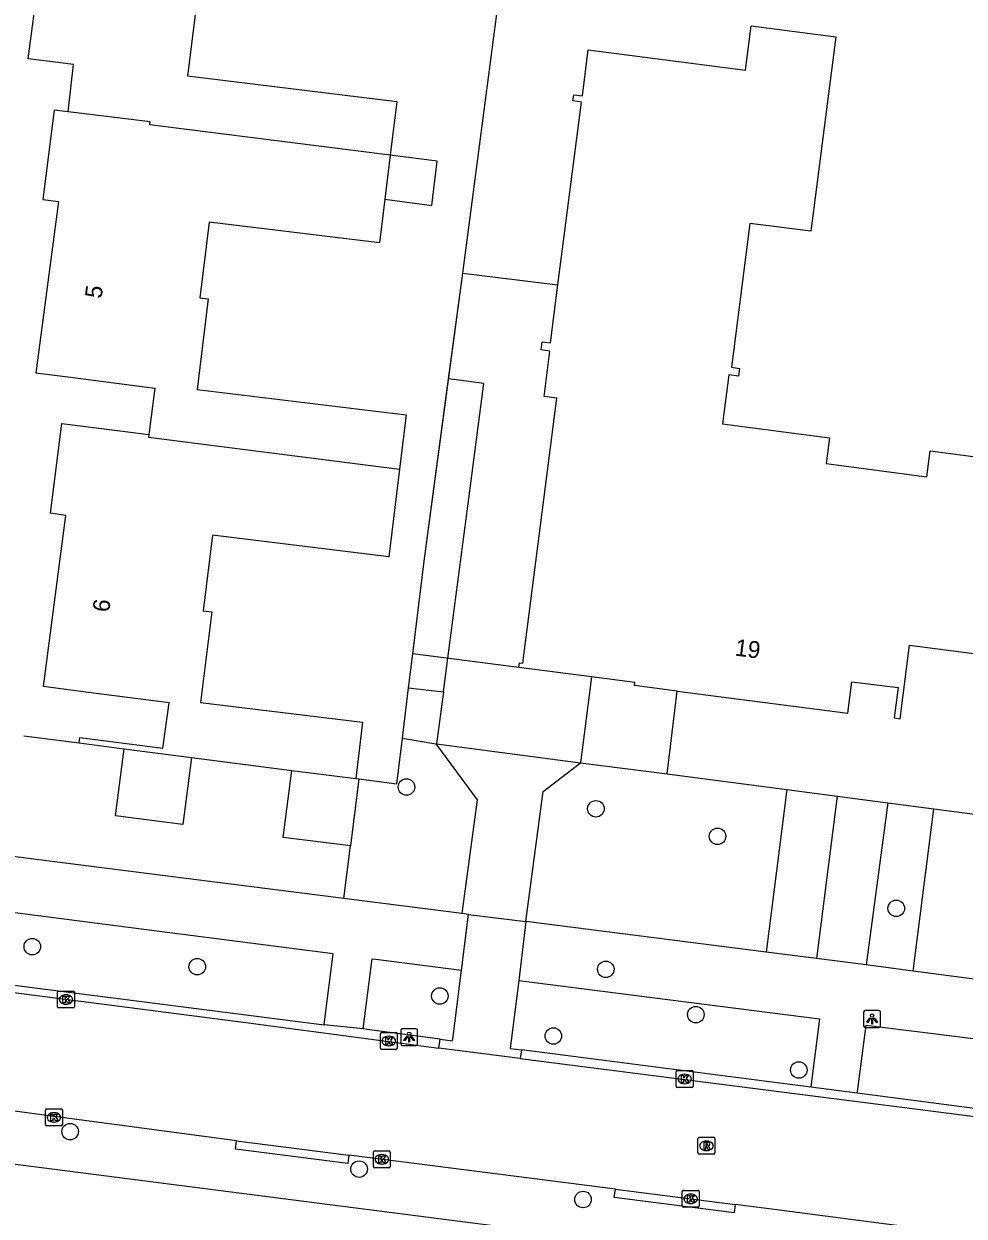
# Model space of a CAD drawing. Extents: x 162186 to 163152, y 385513 to 386513.
# Drawn here: x 162428.7 to 162484.4, y 386032.3 to 386102.8 of the extents above; entities that cross this region are included whole.
import ezdxf

# ---------------------------------------------------------------- set-up
doc = ezdxf.new("R2010")
doc.units = 0
for name, color, linetype in [('IMGEO_Boom', 7, 'Continuous'), ('IMGEO_Groenvoorziening', 7, 'Continuous'), ('IMGEO_Hek', 7, 'Continuous'), ('IMGEO_Kolk', 7, 'Continuous'), ('IMGEO_Lichtpunt', 7, 'Continuous'), ('IMGEO_Pand', 7, 'Continuous'), ('IMGEO_Pand_nummerreeks', 7, 'Continuous'), ('IMGEO_Parkeervlak_open', 7, 'Continuous'), ('IMGEO_Rijbaan_lokaal_open', 7, 'Continuous'), ('IMGEO_Rioolput', 7, 'Continuous'), ('IMGEO_Voetpad_open', 7, 'Continuous')]:
    doc.layers.add(name, color=color, linetype=linetype)

msp = doc.modelspace()

# ---------------------------------------------------------------- linework, layer by layer
at = {"layer": 'IMGEO_Boom'}
for centre in [(162451.366, 386057.668), (162462.574, 386056.38), (162469.77, 386054.75), (162480.341, 386050.488), (162429.227, 386048.224), (162438.987, 386047.037), (162463.156, 386046.884), (162453.342, 386045.303), (162468.485, 386044.202), (162460.056, 386042.937), (162474.576, 386040.923), (162431.465, 386037.28), (162448.562, 386035.061), (162461.812, 386033.263)]:
    msp.add_circle(centre, 0.489, dxfattribs=at)
at = {"layer": 'IMGEO_Groenvoorziening'}
for points in [[(162428.719, 386060.699), (162431.998, 386060.278)], [(162448.556, 386058.142), (162450.787, 386057.854), (162451.121, 386060.554)], [(162438.638, 386059.421), (162438.126, 386055.454), (162434.159, 386055.966), (162434.67, 386059.933)], [(162448.046, 386054.19), (162444.077, 386054.687), (162444.589, 386058.654)], [(162466.784, 386058.45), (162473.878, 386057.522)], [(162448.556, 386058.142), (162448.046, 386054.19)], [(162448.363, 386058.167), (162448.556, 386058.142)], [(162473.878, 386057.522), (162472.641, 386047.895)], [(162473.878, 386057.522), (162476.853, 386057.133)], [(162479.853, 386056.74), (162482.563, 386056.386)], [(162481.339, 386046.773), (162482.563, 386056.386)], [(162482.563, 386056.386), (162495.261, 386054.726), (162500, 386054.106), (162515.064, 386052.135), (162521.578, 386051.283), (162521.727, 386051.263)], [(162447.668, 386051.07), (162448.046, 386054.19)]]:
    msp.add_lwpolyline(points, dxfattribs=at)
at = {"layer": 'IMGEO_Hek'}
for points in [[(162454.696, 386088.073), (162457.574, 386110.037)], [(162452.419, 386071.03), (162454.696, 386088.073)], [(162454.696, 386088.073), (162460.323, 386087.377)], [(162458.017, 386064.739), (162451.74, 386065.549)]]:
    msp.add_lwpolyline(points, dxfattribs=at)
at = {"layer": 'IMGEO_Kolk'}
for p, q in [((162430.723, 386044.669), (162430.723, 386045.521)), ((162430.798, 386045.595), (162431.65, 386045.595)), ((162431.211, 386045.375), (162431.236, 386045.375)), ((162431.724, 386045.521), (162431.724, 386044.669)), ((162431.65, 386044.595), (162430.798, 386044.595)), ((162431.234, 386044.815), (162431.209, 386044.815)), ((162449.822, 386042.214), (162449.822, 386043.066)), ((162449.897, 386043.14), (162450.749, 386043.14)), ((162450.31, 386042.92), (162450.335, 386042.92)), ((162450.823, 386043.066), (162450.823, 386042.214)), ((162450.749, 386042.14), (162449.897, 386042.14)), ((162450.333, 386042.36), (162450.308, 386042.36)), ((162467.32, 386039.968), (162467.32, 386040.82)), ((162467.395, 386040.894), (162468.247, 386040.894)), ((162468.321, 386040.82), (162468.321, 386039.968)), ((162467.831, 386040.114), (162467.806, 386040.114)), ((162467.808, 386040.674), (162467.833, 386040.674)), ((162468.247, 386039.894), (162467.395, 386039.894)), ((162430.081, 386038.621), (162430.933, 386038.621)), ((162430.006, 386037.695), (162430.006, 386038.547)), ((162430.494, 386038.401), (162430.519, 386038.401)), ((162431.007, 386038.547), (162431.007, 386037.695)), ((162430.933, 386037.621), (162430.081, 386037.621)), ((162430.517, 386037.841), (162430.492, 386037.841)), ((162449.409, 386035.217), (162449.409, 386036.069)), ((162449.484, 386036.143), (162450.336, 386036.143)), ((162449.897, 386035.923), (162449.922, 386035.923)), ((162450.41, 386036.069), (162450.41, 386035.217)), ((162450.336, 386035.143), (162449.484, 386035.143)), ((162449.92, 386035.363), (162449.895, 386035.363)), ((162467.678, 386032.88), (162467.678, 386033.732)), ((162467.753, 386033.806), (162468.605, 386033.806)), ((162468.679, 386033.732), (162468.679, 386032.88)), ((162468.189, 386033.026), (162468.164, 386033.026)), ((162468.166, 386033.586), (162468.191, 386033.586)), ((162468.605, 386032.806), (162467.753, 386032.806))]:
    msp.add_line(p, q, dxfattribs=at)
for points in [[(162430.723, 386044.669), (162430.723, 386045.521)], [(162430.798, 386045.595), (162431.65, 386045.595)], [(162431.044, 386045.295), (162431.167, 386045.295), (162431.167, 386045.144), (162431.297, 386045.295), (162431.461, 386045.295), (162431.315, 386045.144), (162431.468, 386044.895), (162431.316, 386044.895), (162431.231, 386045.059), (162431.167, 386044.992), (162431.167, 386044.895), (162431.044, 386044.895), (162431.044, 386045.295)], [(162431.724, 386045.521), (162431.724, 386044.669)], [(162431.65, 386044.595), (162430.798, 386044.595)], [(162449.822, 386042.214), (162449.822, 386043.066)], [(162449.897, 386043.14), (162450.749, 386043.14)], [(162450.143, 386042.84), (162450.266, 386042.84), (162450.266, 386042.689), (162450.396, 386042.84), (162450.56, 386042.84), (162450.414, 386042.689), (162450.567, 386042.44), (162450.415, 386042.44), (162450.33, 386042.604), (162450.266, 386042.537), (162450.266, 386042.44), (162450.143, 386042.44), (162450.143, 386042.84)], [(162450.823, 386043.066), (162450.823, 386042.214)], [(162450.749, 386042.14), (162449.897, 386042.14)], [(162467.32, 386039.968), (162467.32, 386040.82)], [(162467.395, 386040.894), (162468.247, 386040.894)], [(162468.321, 386040.82), (162468.321, 386039.968)], [(162467.641, 386040.594), (162467.764, 386040.594), (162467.764, 386040.443), (162467.894, 386040.594), (162468.058, 386040.594), (162467.912, 386040.443), (162468.065, 386040.194), (162467.913, 386040.194), (162467.828, 386040.358), (162467.764, 386040.291), (162467.764, 386040.194), (162467.641, 386040.194), (162467.641, 386040.594)], [(162468.247, 386039.894), (162467.395, 386039.894)], [(162430.081, 386038.621), (162430.933, 386038.621)], [(162430.006, 386037.695), (162430.006, 386038.547)], [(162430.327, 386038.321), (162430.45, 386038.321), (162430.45, 386038.17), (162430.58, 386038.321), (162430.744, 386038.321), (162430.598, 386038.17), (162430.751, 386037.921), (162430.599, 386037.921), (162430.514, 386038.085), (162430.45, 386038.018), (162430.45, 386037.921), (162430.327, 386037.921), (162430.327, 386038.321)], [(162431.007, 386038.547), (162431.007, 386037.695)], [(162430.933, 386037.621), (162430.081, 386037.621)], [(162449.409, 386035.217), (162449.409, 386036.069)], [(162449.484, 386036.143), (162450.336, 386036.143)], [(162449.73, 386035.843), (162449.853, 386035.843), (162449.853, 386035.692), (162449.983, 386035.843), (162450.147, 386035.843), (162450.001, 386035.692), (162450.154, 386035.443), (162450.002, 386035.443), (162449.917, 386035.607), (162449.853, 386035.54), (162449.853, 386035.443), (162449.73, 386035.443), (162449.73, 386035.843)], [(162450.41, 386036.069), (162450.41, 386035.217)], [(162450.336, 386035.143), (162449.484, 386035.143)], [(162467.678, 386032.88), (162467.678, 386033.732)], [(162467.753, 386033.806), (162468.605, 386033.806)], [(162468.679, 386033.732), (162468.679, 386032.88)], [(162467.999, 386033.506), (162468.122, 386033.506), (162468.122, 386033.355), (162468.252, 386033.506), (162468.416, 386033.506), (162468.27, 386033.355), (162468.423, 386033.106), (162468.271, 386033.106), (162468.186, 386033.27), (162468.122, 386033.203), (162468.122, 386033.106), (162467.999, 386033.106), (162467.999, 386033.506)], [(162468.605, 386032.806), (162467.753, 386032.806)]]:
    msp.add_lwpolyline(points, dxfattribs=at)
for centre, start, end in [((162430.8, 386045.519), 91.55205, 178.44795), ((162430.8, 386045.519), 91.55205, 178.44795), ((162431.648, 386045.519), 1.55205, 88.44795), ((162431.648, 386045.519), 1.55205, 88.44795), ((162430.8, 386044.671), 181.55205, 268.44795), ((162430.8, 386044.671), 181.55205, 268.44795), ((162431.648, 386044.671), 271.55205, 358.44795), ((162431.648, 386044.671), 271.55205, 358.44795), ((162449.899, 386043.064), 91.55205, 178.44795), ((162449.899, 386043.064), 91.55205, 178.44795), ((162450.747, 386043.064), 1.55205, 88.44795), ((162450.747, 386043.064), 1.55205, 88.44795), ((162449.899, 386042.216), 181.55205, 268.44795), ((162449.899, 386042.216), 181.55205, 268.44795), ((162450.747, 386042.216), 271.55205, 358.44795), ((162450.747, 386042.216), 271.55205, 358.44795), ((162467.397, 386040.818), 91.55205, 178.44795), ((162467.397, 386040.818), 91.55205, 178.44795), ((162468.245, 386040.818), 1.55205, 88.44795), ((162468.245, 386040.818), 1.55205, 88.44795), ((162467.397, 386039.97), 181.55205, 268.44795), ((162467.397, 386039.97), 181.55205, 268.44795), ((162468.245, 386039.97), 271.55205, 358.44795), ((162468.245, 386039.97), 271.55205, 358.44795), ((162430.083, 386038.545), 91.55205, 178.44795), ((162430.083, 386038.545), 91.55205, 178.44795), ((162430.931, 386038.545), 1.55205, 88.44795), ((162430.931, 386038.545), 1.55205, 88.44795), ((162430.083, 386037.697), 181.55205, 268.44795), ((162430.083, 386037.697), 181.55205, 268.44795), ((162430.931, 386037.697), 271.55205, 358.44795), ((162430.931, 386037.697), 271.55205, 358.44795), ((162449.486, 386036.067), 91.55205, 178.44795), ((162449.486, 386036.067), 91.55205, 178.44795), ((162450.334, 386036.067), 1.55205, 88.44795), ((162450.334, 386036.067), 1.55205, 88.44795), ((162449.486, 386035.219), 181.55205, 268.44795), ((162449.486, 386035.219), 181.55205, 268.44795), ((162450.334, 386035.219), 271.55205, 358.44795), ((162450.334, 386035.219), 271.55205, 358.44795), ((162467.755, 386033.73), 91.55205, 178.44795), ((162467.755, 386033.73), 91.55205, 178.44795), ((162468.603, 386033.73), 1.55205, 88.44795), ((162468.603, 386033.73), 1.55205, 88.44795), ((162467.755, 386032.882), 181.55205, 268.44795), ((162467.755, 386032.882), 181.55205, 268.44795), ((162468.603, 386032.882), 271.55205, 358.44795), ((162468.603, 386032.882), 271.55205, 358.44795)]:
    msp.add_arc(centre, 0.0765, start, end, dxfattribs=at)
for centre, major_axis, ratio, start_param, end_param in [((162431.21, 386045.095), (-0.387, 0.002), 0.722429, 4.712389, 7.853982), ((162431.235, 386045.095), (-0.39, 0.002), 0.717154, 1.570796, 4.712389), ((162450.309, 386042.64), (-0.387, 0.002), 0.722429, 4.712389, 7.853982), ((162450.334, 386042.64), (-0.39, 0.002), 0.717154, 1.570796, 4.712389), ((162467.807, 386040.394), (-0.387, 0.002), 0.722429, 4.712389, 7.853982), ((162467.832, 386040.394), (-0.39, 0.002), 0.717154, 1.570796, 4.712389), ((162430.493, 386038.121), (-0.387, 0.002), 0.722429, 4.712389, 7.853982), ((162430.518, 386038.121), (-0.39, 0.002), 0.717154, 1.570796, 4.712389), ((162449.896, 386035.643), (-0.387, 0.002), 0.722429, 4.712389, 7.853982), ((162449.921, 386035.643), (-0.39, 0.002), 0.717154, 1.570796, 4.712389), ((162468.165, 386033.306), (-0.387, 0.002), 0.722429, 4.712389, 7.853982), ((162468.19, 386033.306), (-0.39, 0.002), 0.717154, 1.570796, 4.712389)]:
    msp.add_ellipse(centre, major_axis=major_axis, ratio=ratio, start_param=start_param, end_param=end_param, dxfattribs=at)
at = {"layer": 'IMGEO_Lichtpunt'}
for p, q in [((162478.412, 386044.347), (162478.412, 386043.54)), ((162478.412, 386044.347), (162478.412, 386043.54)), ((162479.314, 386044.442), (162478.506, 386044.442)), ((162479.314, 386044.442), (162478.506, 386044.442)), ((162479.408, 386043.54), (162479.408, 386044.347)), ((162479.408, 386043.54), (162479.408, 386044.347)), ((162451.026, 386043.275), (162451.026, 386042.468)), ((162451.026, 386043.275), (162451.026, 386042.468)), ((162451.928, 386043.37), (162451.12, 386043.37)), ((162451.928, 386043.37), (162451.12, 386043.37)), ((162452.022, 386042.468), (162452.022, 386043.275)), ((162452.022, 386042.468), (162452.022, 386043.275)), ((162478.506, 386043.446), (162479.314, 386043.446)), ((162478.506, 386043.446), (162479.314, 386043.446)), ((162451.12, 386042.374), (162451.928, 386042.374)), ((162451.12, 386042.374), (162451.928, 386042.374))]:
    msp.add_line(p, q, dxfattribs=at)
for points in [[(162478.786, 386044.011), (162478.825, 386043.983), (162478.637, 386043.721), (162478.599, 386043.748), (162478.786, 386044.011)], [(162478.888, 386043.963), (162478.935, 386043.963), (162478.935, 386043.641), (162478.888, 386043.641), (162478.888, 386043.963)], [(162478.998, 386043.983), (162479.036, 386044.01), (162479.223, 386043.748), (162479.184, 386043.72), (162478.998, 386043.983)], [(162451.4, 386042.939), (162451.439, 386042.911), (162451.251, 386042.649), (162451.213, 386042.676), (162451.4, 386042.939)], [(162451.502, 386042.891), (162451.549, 386042.891), (162451.549, 386042.569), (162451.502, 386042.569), (162451.502, 386042.891)], [(162451.612, 386042.911), (162451.65, 386042.938), (162451.837, 386042.676), (162451.798, 386042.648), (162451.612, 386042.911)]]:
    msp.add_lwpolyline(points, dxfattribs=at)
for centre in [(162478.911, 386044.145), (162451.525, 386043.073)]:
    msp.add_circle(centre, 0.0994, dxfattribs=at)
for centre, start, end in [((162478.506, 386044.347), 90, 180), ((162478.506, 386044.347), 90, 180), ((162479.314, 386044.347), 0, 90), ((162479.314, 386044.347), 0, 90), ((162478.506, 386043.54), 180, 270), ((162478.506, 386043.54), 180, 270), ((162479.314, 386043.54), 270, 0), ((162479.314, 386043.54), 270, 360), ((162451.12, 386043.275), 90, 180), ((162451.12, 386043.275), 90, 180), ((162451.928, 386043.275), 0, 90), ((162451.928, 386043.275), 0, 90), ((162451.12, 386042.468), 180, 270), ((162451.12, 386042.468), 180, 270), ((162451.928, 386042.468), 270, 0), ((162451.928, 386042.468), 270, 360)]:
    msp.add_arc(centre, 0.0946, start, end, dxfattribs=at)
at = {"layer": 'IMGEO_Pand'}
for points in [[(162431.348, 386097.618), (162431.658, 386100.411), (162430.892, 386100.505), (162428.983, 386100.738), (162430.323, 386110.881), (162429.428, 386111), (162430.108, 386116.262)], [(162449.855, 386113.717), (162449.205, 386108.402), (162439.124, 386109.633), (162438.579, 386105.162), (162439.074, 386105.102), (162438.419, 386099.738), (162450.792, 386098.225), (162450.404, 386095.045)], [(162460.323, 386087.377), (162461.718, 386098.188), (162461.216, 386098.253), (162461.264, 386098.622), (162461.772, 386098.556), (162462.124, 386101.287), (162471.428, 386100.086), (162471.765, 386102.696), (162476.768, 386102.051), (162475.283, 386090.549), (162471.688, 386091.014), (162470.588, 386082.498), (162471.059, 386082.437), (162471, 386081.983), (162470.441, 386082.056), (162470.066, 386079.151), (162476.389, 386078.335), (162476.19, 386076.797), (162482.159, 386076.027), (162482.356, 386077.553), (162485.644, 386077.128)], [(162431.348, 386097.618), (162430.532, 386097.717), (162429.857, 386092.423), (162430.77, 386092.306), (162429.444, 386082.164), (162431.329, 386081.925), (162436.473, 386081.271), (162436.124, 386078.528)], [(162450.404, 386095.045), (162436.186, 386096.848), (162436.208, 386097.025), (162431.348, 386097.618)], [(162450.404, 386095.045), (162450.086, 386092.442)], [(162450.086, 386092.442), (162452.861, 386092.073), (162453.181, 386094.693), (162450.404, 386095.045)], [(162450.086, 386092.442), (162449.77, 386089.853), (162439.688, 386091.084), (162439.142, 386086.614), (162439.638, 386086.553), (162438.983, 386081.189), (162451.347, 386079.68), (162450.955, 386076.471)], [(162462.315, 386064.184), (162458.017, 386064.739), (162458.053, 386065.02), (162458.242, 386064.996), (162460.265, 386080.665), (162459.505, 386080.763), (162459.853, 386083.461), (162459.339, 386083.527), (162459.401, 386084.01), (162459.88, 386083.949), (162460.323, 386087.377)], [(162431.998, 386060.278), (162432.039, 386060.596), (162436.949, 386059.963), (162437.333, 386062.638), (162432.386, 386063.284), (162429.896, 386063.609), (162431.219, 386073.74), (162430.298, 386073.878), (162430.975, 386079.181), (162436.124, 386078.528)], [(162436.124, 386078.528), (162436.104, 386078.372), (162450.955, 386076.471)], [(162450.955, 386076.471), (162450.321, 386071.286), (162439.892, 386072.56), (162439.346, 386068.09), (162439.841, 386068.029), (162439.187, 386062.665), (162448.77, 386061.495), (162448.363, 386058.167)], [(162467.38, 386063.345), (162477.483, 386062.04), (162477.722, 386063.898), (162480.453, 386063.545), (162480.222, 386061.752), (162480.573, 386061.707), (162481.133, 386066.05), (162500, 386063.614), (162518.109, 386061.276), (162518.132, 386061.454), (162521.5, 386061.019), (162522.905, 386071.008)], [(162467.38, 386063.345), (162464.852, 386063.671), (162464.875, 386063.854), (162462.315, 386064.184)], [(162431.998, 386060.278), (162434.67, 386059.933)], [(162434.67, 386059.933), (162438.638, 386059.421)], [(162438.638, 386059.421), (162444.589, 386058.654)], [(162444.589, 386058.654), (162448.363, 386058.167)]]:
    msp.add_lwpolyline(points, dxfattribs=at)
at = {"layer": 'IMGEO_Parkeervlak_open'}
for points in [[(162451.491, 386063.543), (162451.74, 386065.549), (162452.419, 386071.03), (162453.861, 386081.821)], [(162466.784, 386058.45), (162467.38, 386063.345)], [(162461.659, 386059.103), (162466.784, 386058.45)]]:
    msp.add_lwpolyline(points, dxfattribs=at)
at = {"layer": 'IMGEO_Rijbaan_lokaal_open'}
for points in [[(162453.861, 386081.821), (162454.696, 386088.073), (162460.323, 386087.377)], [(162453.547, 386063.289), (162453.809, 386065.282), (162454.992, 386074.289), (162455.945, 386081.543), (162453.861, 386081.821)], [(162462.315, 386064.184), (162461.659, 386059.103)], [(162453.547, 386063.289), (162453.145, 386060.221)], [(162453.145, 386060.221), (162461.659, 386059.103)], [(162416.511, 386047), (162441.857, 386043.741), (162453.274, 386042.224)], [(162458.097, 386041.609), (162453.274, 386042.224)], [(162458.097, 386041.609), (162500, 386036.267), (162530.454, 386032.366)], [(162441.318, 386036.733), (162411.465, 386040.722)], [(162441.318, 386036.733), (162447.955, 386035.886)], [(162463.723, 386033.874), (162447.955, 386035.886)], [(162463.723, 386033.874), (162470.821, 386032.968)], [(162489.419, 386030.537), (162472.666, 386032.732), (162470.821, 386032.968)]]:
    msp.add_lwpolyline(points, dxfattribs=at)
at = {"layer": 'IMGEO_Rioolput'}
for p, q in [((162468.612, 386036.016), (162468.612, 386036.868)), ((162468.687, 386036.942), (162469.539, 386036.942)), ((162469.1, 386036.722), (162469.125, 386036.722)), ((162469.613, 386036.868), (162469.613, 386036.016)), ((162469.539, 386035.942), (162468.687, 386035.942)), ((162469.123, 386036.162), (162469.098, 386036.162))]:
    msp.add_line(p, q, dxfattribs=at)
for points in [[(162468.612, 386036.016), (162468.612, 386036.868)], [(162468.687, 386036.942), (162469.539, 386036.942)], [(162469.201, 386036.64), (162468.949, 386036.642), (162468.949, 386036.242)], [(162469.127, 386036.561), (162469.073, 386036.561), (162469.073, 386036.48)], [(162469.073, 386036.48), (162469.125, 386036.48)], [(162469.613, 386036.868), (162469.613, 386036.016)], [(162469.539, 386035.942), (162468.687, 386035.942)], [(162468.949, 386036.242), (162469.073, 386036.242), (162469.073, 386036.404), (162469.084, 386036.404)], [(162469.131, 386036.375), (162469.202, 386036.242), (162469.342, 386036.242), (162469.277, 386036.368)]]:
    msp.add_lwpolyline(points, dxfattribs=at)
for centre, radius, start, end in [((162468.689, 386036.866), 0.0765, 91.55205, 178.44795), ((162468.689, 386036.866), 0.0765, 91.55205, 178.44795), ((162469.109, 386036.669), 0.19, 274.7715, 282.96867), ((162469.133, 386036.465), 0.0964, 77.00612, 93.18647), ((162469.147, 386036.522), 0.0378, 276.66336, 79.67722), ((162469.2, 386036.53), 0.109, 350.36119, 89.41601), ((162469.198, 386036.53), 0.112, 277.58423, 350.98172), ((162469.537, 386036.866), 0.0765, 1.55205, 88.44795), ((162469.537, 386036.866), 0.0765, 1.55205, 88.44795), ((162468.689, 386036.018), 0.0765, 181.55205, 268.44795), ((162468.689, 386036.018), 0.0765, 181.55205, 268.44795), ((162469.083, 386036.351), 0.0533, 26.02933, 88.69889), ((162469.182, 386036.315), 0.108, 29.51342, 73.79051), ((162469.537, 386036.018), 0.0765, 271.55205, 358.44795), ((162469.537, 386036.018), 0.0765, 271.55205, 358.44795)]:
    msp.add_arc(centre, radius, start, end, dxfattribs=at)
for centre, major_axis, ratio, start_param, end_param in [((162469.099, 386036.442), (-0.387, 0.002), 0.722429, 4.712389, 7.853982), ((162469.124, 386036.442), (-0.39, 0.002), 0.717154, 1.570796, 4.712389)]:
    msp.add_ellipse(centre, major_axis=major_axis, ratio=ratio, start_param=start_param, end_param=end_param, dxfattribs=at)
at = {"layer": 'IMGEO_Voetpad_open'}
for points in [[(162451.121, 386060.554), (162451.491, 386063.543)], [(162451.491, 386063.543), (162453.547, 386063.289)], [(162451.121, 386060.554), (162453.108, 386060.226)], [(162453.108, 386060.226), (162453.145, 386060.221)], [(162453.108, 386060.226), (162455.557, 386056.911), (162454.648, 386050.183)], [(162458.436, 386049.702), (162459.455, 386057.4), (162461.659, 386059.103)], [(162476.853, 386057.133), (162475.618, 386047.518)], [(162476.853, 386057.133), (162479.853, 386056.74)], [(162479.853, 386056.74), (162478.571, 386047.142)], [(162447.668, 386051.07), (162429.615, 386053.363), (162415.88, 386055.128)], [(162446.5, 386043.591), (162446.543, 386043.929), (162447.038, 386047.8), (162436.597, 386049.145), (162421.308, 386051.115), (162417.099, 386051.668)], [(162454.648, 386050.183), (162447.668, 386051.07)], [(162454.616, 386046.823), (162455.042, 386050.133)], [(162455.042, 386050.133), (162454.648, 386050.183)], [(162455.042, 386050.133), (162458.436, 386049.702)], [(162458.436, 386049.702), (162458.011, 386046.211)], [(162472.641, 386047.895), (162458.436, 386049.702)], [(162475.618, 386047.518), (162472.641, 386047.895)], [(162416.565, 386047.431), (162446.5, 386043.591)], [(162448.803, 386043.361), (162449.337, 386047.503), (162449.544, 386047.477), (162454.616, 386046.823)], [(162478.571, 386047.142), (162475.618, 386047.518)], [(162481.339, 386046.773), (162478.571, 386047.142)], [(162453.368, 386042.756), (162454.094, 386042.659), (162454.126, 386042.899), (162454.616, 386046.823)], [(162520.412, 386041.654), (162500, 386044.328), (162481.339, 386046.773)], [(162458.011, 386046.211), (162457.543, 386042.52), (162457.503, 386042.203), (162458.164, 386042.118)], [(162458.011, 386046.211), (162475.809, 386043.954), (162475.336, 386040.252), (162475.292, 386039.909)], [(162448.803, 386043.361), (162446.5, 386043.591)], [(162478.033, 386039.554), (162478.063, 386039.785), (162478.556, 386043.58), (162520.029, 386038.411), (162519.545, 386034.527), (162519.499, 386034.169)], [(162453.368, 386042.756), (162449.031, 386043.331), (162448.803, 386043.361)], [(162453.274, 386042.224), (162453.368, 386042.756)], [(162458.164, 386042.118), (162458.097, 386041.609)], [(162475.292, 386039.909), (162458.164, 386042.118)], [(162478.033, 386039.554), (162475.292, 386039.909)], [(162519.499, 386034.169), (162500.92, 386036.604), (162498.29, 386036.923), (162487.53, 386038.32), (162478.033, 386039.554)], [(162447.955, 386035.886), (162447.892, 386035.399), (162441.255, 386036.248), (162441.318, 386036.733)], [(162525.924, 386022.81), (162500, 386026.135), (162427.629, 386035.417), (162425.539, 386035.686)], [(162470.821, 386032.968), (162470.758, 386032.473), (162463.66, 386033.381), (162463.723, 386033.874)]]:
    msp.add_lwpolyline(points, dxfattribs=at)

# ---------------------------------------------------------------- texts
at = {"layer": 'IMGEO_Pand_nummerreeks'}
for s, rotation, p in [('5', 82.55176, (162433.324, 386086.537)), ('6', 82.55989, (162433.774, 386067.977)), ('19', 352.64322, (162470.761, 386065.449))]:
    msp.add_text(s, height=1, rotation=rotation, dxfattribs=at).set_placement(p)

doc.saveas('drawing.dxf')
